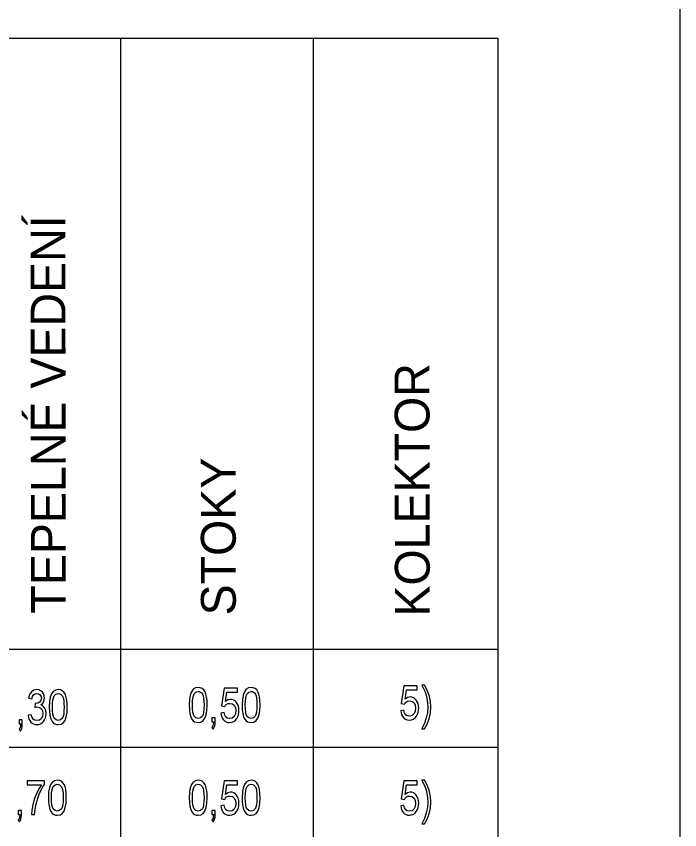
# Model space of a CAD drawing. Extents: x -480568.5 to -480543.1, y -1126945.4 to -1126930.6.
# Drawn here: x -480544.927 to -480543.093, y -1126938.768 to -1126936.519 of the extents above; entities that cross this region are included whole.
import ezdxf

# ---------------------------------------------------------------- set-up
doc = ezdxf.new("R2010")
doc.units = 0
doc.layers.add('detaily', color=7, linetype='Continuous')
doc.layers.add('EL1', color=7, linetype='Continuous')

msp = doc.modelspace()

# ---------------------------------------------------------------- linework, layer by layer
at = {"layer": 'detaily'}
msp.add_line((-480543.0929, -1126930.5663), (-480543.0929, -1126945.4163), dxfattribs=at)
msp.add_lwpolyline([(-480543.5956, -1126939.8124), (-480551.8459, -1126939.8124), (-480551.8459, -1126936.5789), (-480543.5956, -1126936.5789)], close=True, dxfattribs=at)
at = {"layer": 'EL1'}
for p, q in [((-480544.6383, -1126939.8121), (-480544.6383, -1126936.5789)), ((-480544.1063, -1126936.5789), (-480544.1063, -1126939.8121)), ((-480550.8407, -1126938.2688), (-480543.5956, -1126938.2688)), ((-480549.8036, -1126938.5394), (-480543.5956, -1126938.5394))]:
    msp.add_line(p, q, dxfattribs=at)
for points in [[(-480544.8942, -1126938.4517), (-480544.8934, -1126938.4571), (-480544.8919, -1126938.462), (-480544.8897, -1126938.4664), (-480544.8867, -1126938.4702), (-480544.8832, -1126938.4733), (-480544.8793, -1126938.4755), (-480544.8749, -1126938.4769), (-480544.8701, -1126938.4773), (-480544.8648, -1126938.4767), (-480544.86, -1126938.4751), (-480544.8557, -1126938.4723), (-480544.8518, -1126938.4684), (-480544.8486, -1126938.4638), (-480544.8464, -1126938.4586), (-480544.845, -1126938.453), (-480544.8445, -1126938.4468), (-480544.8456, -1126938.4382), (-480544.8486, -1126938.4311), (-480544.8533, -1126938.4259), (-480544.8593, -1126938.4229), (-480544.8548, -1126938.4195), (-480544.8515, -1126938.4151), (-480544.8496, -1126938.41), (-480544.8489, -1126938.4043), (-480544.8496, -1126938.3982), (-480544.8516, -1126938.3925), (-480544.8549, -1126938.3875), (-480544.8594, -1126938.3837), (-480544.8647, -1126938.3813), (-480544.8705, -1126938.3805), (-480544.8786, -1126938.382), (-480544.8852, -1126938.3867), (-480544.8901, -1126938.3942), (-480544.8928, -1126938.4042), (-480544.884, -1126938.406), (-480544.8823, -1126938.3997), (-480544.8793, -1126938.3951), (-480544.8752, -1126938.3923), (-480544.8702, -1126938.3914), (-480544.8652, -1126938.3924), (-480544.8612, -1126938.3952), (-480544.8586, -1126938.3995), (-480544.8577, -1126938.4047), (-480544.8589, -1126938.411), (-480544.8625, -1126938.4155), (-480544.8676, -1126938.4181), (-480544.8733, -1126938.419), (-480544.8748, -1126938.4188), (-480544.8759, -1126938.4298), (-480544.869, -1126938.4285), (-480544.8628, -1126938.4298), (-480544.8577, -1126938.4337), (-480544.8544, -1126938.4395), (-480544.8533, -1126938.4468), (-480544.8544, -1126938.4544), (-480544.8577, -1126938.4607), (-480544.8629, -1126938.4649), (-480544.8698, -1126938.4663), (-480544.8757, -1126938.4654), (-480544.8801, -1126938.4625), (-480544.8833, -1126938.4574), (-480544.8855, -1126938.4499)], [(-480544.8357, -1126938.4289), (-480544.8352, -1126938.4414), (-480544.8338, -1126938.4521), (-480544.8315, -1126938.4612), (-480544.8282, -1126938.4684), (-480544.8248, -1126938.4723), (-480544.8207, -1126938.4751), (-480544.8161, -1126938.4767), (-480544.8109, -1126938.4773), (-480544.8032, -1126938.476), (-480544.797, -1126938.4722), (-480544.7922, -1126938.4657), (-480544.7888, -1126938.4563), (-480544.7867, -1126938.4441), (-480544.786, -1126938.4289), (-480544.7864, -1126938.4163), (-480544.7877, -1126938.4065), (-480544.7897, -1126938.3989), (-480544.7921, -1126938.3924), (-480544.7953, -1126938.3873), (-480544.7997, -1126938.3836), (-480544.805, -1126938.3812), (-480544.8109, -1126938.3805), (-480544.8185, -1126938.3818), (-480544.8247, -1126938.3856), (-480544.8295, -1126938.3921), (-480544.8329, -1126938.4014), (-480544.835, -1126938.4136)], [(-480544.4489, -1126938.4232), (-480544.4484, -1126938.4357), (-480544.447, -1126938.4464), (-480544.4446, -1126938.4554), (-480544.4413, -1126938.4626), (-480544.4379, -1126938.4665), (-480544.4339, -1126938.4693), (-480544.4292, -1126938.471), (-480544.424, -1126938.4715), (-480544.4164, -1126938.4702), (-480544.4102, -1126938.4664), (-480544.4054, -1126938.4599), (-480544.4019, -1126938.4506), (-480544.3999, -1126938.4384), (-480544.3992, -1126938.4232), (-480544.3996, -1126938.4105), (-480544.4009, -1126938.4008), (-480544.4028, -1126938.3931), (-480544.4052, -1126938.3867), (-480544.4085, -1126938.3816), (-480544.4129, -1126938.3778), (-480544.4182, -1126938.3755), (-480544.424, -1126938.3747), (-480544.4316, -1126938.376), (-480544.4378, -1126938.3798), (-480544.4426, -1126938.3864), (-480544.4461, -1126938.3956), (-480544.4482, -1126938.4079)], [(-480544.4401, -1126938.4231), (-480544.4398, -1126938.4128), (-480544.4389, -1126938.4042), (-480544.4374, -1126938.3974), (-480544.4354, -1126938.3922), (-480544.4303, -1126938.3873), (-480544.4241, -1126938.3857), (-480544.4207, -1126938.3862), (-480544.4176, -1126938.3875), (-480544.4148, -1126938.3899), (-480544.4124, -1126938.3931), (-480544.4105, -1126938.3978), (-480544.4091, -1126938.4043), (-480544.4082, -1126938.4128), (-480544.4079, -1126938.4231), (-480544.4082, -1126938.4338), (-480544.4091, -1126938.4425), (-480544.4106, -1126938.4491), (-480544.4126, -1126938.4536), (-480544.4178, -1126938.4588), (-480544.424, -1126938.4606), (-480544.4303, -1126938.4588), (-480544.4355, -1126938.4536), (-480544.4375, -1126938.4491), (-480544.439, -1126938.4425), (-480544.4398, -1126938.4339)], [(-480544.3611, -1126938.446), (-480544.3603, -1126938.4515), (-480544.3588, -1126938.4564), (-480544.3566, -1126938.4608), (-480544.3537, -1126938.4645), (-480544.3503, -1126938.4676), (-480544.3463, -1126938.4698), (-480544.3419, -1126938.4711), (-480544.337, -1126938.4715), (-480544.3311, -1126938.4708), (-480544.3259, -1126938.4687), (-480544.3213, -1126938.4651), (-480544.3173, -1126938.4601), (-480544.3148, -1126938.4553), (-480544.3129, -1126938.45), (-480544.3118, -1126938.4443), (-480544.3114, -1126938.4381), (-480544.3118, -1126938.4317), (-480544.3131, -1126938.4259), (-480544.3152, -1126938.4207), (-480544.3182, -1126938.4161), (-480544.3218, -1126938.4124), (-480544.3257, -1126938.4097), (-480544.33, -1126938.4081), (-480544.3347, -1126938.4076), (-480544.342, -1126938.4092), (-480544.3489, -1126938.4139), (-480544.3451, -1126938.3875), (-480544.3158, -1126938.3875), (-480544.3158, -1126938.3765), (-480544.3523, -1126938.3765), (-480544.3596, -1126938.4259), (-480544.3509, -1126938.4277), (-480544.3485, -1126938.424), (-480544.3454, -1126938.4211), (-480544.3416, -1126938.4192), (-480544.3367, -1126938.4186), (-480544.3294, -1126938.4199), (-480544.3242, -1126938.424), (-480544.3212, -1126938.4304), (-480544.3202, -1126938.4388), (-480544.3213, -1126938.4477), (-480544.3245, -1126938.4546), (-480544.3298, -1126938.4591), (-480544.337, -1126938.4606), (-480544.3429, -1126938.4596), (-480544.3474, -1126938.4565), (-480544.3505, -1126938.4513), (-480544.3523, -1126938.4441)], [(-480544.3026, -1126938.4232), (-480544.3021, -1126938.4357), (-480544.3007, -1126938.4464), (-480544.2984, -1126938.4554), (-480544.295, -1126938.4626), (-480544.2916, -1126938.4665), (-480544.2876, -1126938.4693), (-480544.283, -1126938.471), (-480544.2777, -1126938.4715), (-480544.2701, -1126938.4702), (-480544.2639, -1126938.4664), (-480544.2591, -1126938.4599), (-480544.2557, -1126938.4506), (-480544.2536, -1126938.4384), (-480544.2529, -1126938.4232), (-480544.2533, -1126938.4105), (-480544.2546, -1126938.4008), (-480544.2566, -1126938.3931), (-480544.259, -1126938.3867), (-480544.2622, -1126938.3816), (-480544.2666, -1126938.3778), (-480544.2719, -1126938.3755), (-480544.2777, -1126938.3747), (-480544.2853, -1126938.376), (-480544.2915, -1126938.3798), (-480544.2963, -1126938.3864), (-480544.2998, -1126938.3956), (-480544.3019, -1126938.4079)], [(-480544.2938, -1126938.4231), (-480544.2935, -1126938.4128), (-480544.2926, -1126938.4042), (-480544.2912, -1126938.3974), (-480544.2891, -1126938.3922), (-480544.2841, -1126938.3873), (-480544.2778, -1126938.3857), (-480544.2744, -1126938.3862), (-480544.2713, -1126938.3875), (-480544.2685, -1126938.3899), (-480544.2661, -1126938.3931), (-480544.2642, -1126938.3978), (-480544.2628, -1126938.4043), (-480544.2619, -1126938.4128), (-480544.2617, -1126938.4231), (-480544.2619, -1126938.4338), (-480544.2628, -1126938.4425), (-480544.2643, -1126938.4491), (-480544.2663, -1126938.4536), (-480544.2715, -1126938.4588), (-480544.2777, -1126938.4606), (-480544.284, -1126938.4588), (-480544.2892, -1126938.4536), (-480544.2912, -1126938.4491), (-480544.2927, -1126938.4425), (-480544.2935, -1126938.4339)], [(-480543.8641, -1126938.4394), (-480543.8633, -1126938.4449), (-480543.8619, -1126938.4498), (-480543.8597, -1126938.4542), (-480543.8568, -1126938.458), (-480543.8533, -1126938.4611), (-480543.8494, -1126938.4632), (-480543.845, -1126938.4645), (-480543.8401, -1126938.465), (-480543.8342, -1126938.4643), (-480543.8289, -1126938.4621), (-480543.8243, -1126938.4586), (-480543.8204, -1126938.4536), (-480543.8178, -1126938.4487), (-480543.8159, -1126938.4434), (-480543.8148, -1126938.4377), (-480543.8144, -1126938.4315), (-480543.8149, -1126938.4251), (-480543.8161, -1126938.4193), (-480543.8183, -1126938.4142), (-480543.8212, -1126938.4096), (-480543.8248, -1126938.4058), (-480543.8287, -1126938.4032), (-480543.8331, -1126938.4016), (-480543.8378, -1126938.401), (-480543.845, -1126938.4026), (-480543.8519, -1126938.4074), (-480543.8481, -1126938.3809), (-480543.8188, -1126938.3809), (-480543.8188, -1126938.37), (-480543.8554, -1126938.37), (-480543.8627, -1126938.4193), (-480543.8539, -1126938.4211), (-480543.8515, -1126938.4175), (-480543.8485, -1126938.4145), (-480543.8446, -1126938.4126), (-480543.8398, -1126938.412), (-480543.8324, -1126938.4134), (-480543.8273, -1126938.4174), (-480543.8242, -1126938.4238), (-480543.8232, -1126938.4322), (-480543.8243, -1126938.4411), (-480543.8276, -1126938.448), (-480543.8329, -1126938.4525), (-480543.84, -1126938.454), (-480543.846, -1126938.453), (-480543.8504, -1126938.4499), (-480543.8536, -1126938.4448), (-480543.8554, -1126938.4376)], [(-480543.7983, -1126938.4887), (-480543.7915, -1126938.4759), (-480543.7859, -1126938.4611), (-480543.782, -1126938.445), (-480543.7808, -1126938.4284), (-480543.7817, -1126938.4138), (-480543.7846, -1126938.3998), (-480543.7902, -1126938.3839), (-480543.7983, -1126938.3681), (-480543.8056, -1126938.3681), (-480543.797, -1126938.387), (-480543.794, -1126938.3958), (-480543.7918, -1126938.405), (-480543.7901, -1126938.4167), (-480543.7895, -1126938.4284), (-480543.7905, -1126938.4435), (-480543.7936, -1126938.4586), (-480543.7986, -1126938.4737), (-480543.8056, -1126938.4887)], [(-480544.8269, -1126938.4289), (-480544.8267, -1126938.4185), (-480544.8258, -1126938.4099), (-480544.8243, -1126938.4031), (-480544.8222, -1126938.398), (-480544.8172, -1126938.3931), (-480544.811, -1126938.3914), (-480544.8075, -1126938.3919), (-480544.8044, -1126938.3933), (-480544.8017, -1126938.3956), (-480544.7992, -1126938.3989), (-480544.7973, -1126938.4035), (-480544.7959, -1126938.4101), (-480544.7951, -1126938.4186), (-480544.7948, -1126938.4289), (-480544.7951, -1126938.4396), (-480544.7959, -1126938.4482), (-480544.7974, -1126938.4548), (-480544.7994, -1126938.4593), (-480544.8046, -1126938.4646), (-480544.8109, -1126938.4663), (-480544.8171, -1126938.4646), (-480544.8223, -1126938.4593), (-480544.8244, -1126938.4548), (-480544.8258, -1126938.4482), (-480544.8267, -1126938.4396)], [(-480544.9191, -1126938.4755), (-480544.9147, -1126938.4755), (-480544.9159, -1126938.4851), (-480544.9172, -1126938.488), (-480544.9191, -1126938.4901), (-480544.9162, -1126938.4956), (-480544.9136, -1126938.4924), (-480544.9117, -1126938.4881), (-480544.9107, -1126938.4825), (-480544.9103, -1126938.4755), (-480544.9103, -1126938.4645), (-480544.9191, -1126938.4645)], [(-480544.386, -1126938.4697), (-480544.3816, -1126938.4697), (-480544.3827, -1126938.4793), (-480544.3841, -1126938.4822), (-480544.386, -1126938.4843), (-480544.383, -1126938.4898), (-480544.3804, -1126938.4866), (-480544.3786, -1126938.4824), (-480544.3775, -1126938.4768), (-480544.3772, -1126938.4697), (-480544.3772, -1126938.4588), (-480544.386, -1126938.4588)], [(-480544.8969, -1126938.6439), (-480544.8574, -1126938.6439), (-480544.8646, -1126938.6552), (-480544.8714, -1126938.6687), (-480544.8772, -1126938.6836), (-480544.8815, -1126938.6991), (-480544.8842, -1126938.7138), (-480544.8852, -1126938.7261), (-480544.8764, -1126938.7261), (-480544.8752, -1126938.7125), (-480544.873, -1126938.7001), (-480544.8685, -1126938.6835), (-480544.8624, -1126938.6673), (-480544.8556, -1126938.653), (-480544.8486, -1126938.6418), (-480544.8486, -1126938.6329), (-480544.8969, -1126938.6329)], [(-480544.8383, -1126938.6795), (-480544.8379, -1126938.6921), (-480544.8365, -1126938.7028), (-480544.8341, -1126938.7118), (-480544.8308, -1126938.719), (-480544.8274, -1126938.7229), (-480544.8234, -1126938.7257), (-480544.8187, -1126938.7274), (-480544.8135, -1126938.7279), (-480544.8059, -1126938.7266), (-480544.7997, -1126938.7228), (-480544.7949, -1126938.7163), (-480544.7914, -1126938.707), (-480544.7894, -1126938.6948), (-480544.7887, -1126938.6795), (-480544.7891, -1126938.6669), (-480544.7904, -1126938.6571), (-480544.7923, -1126938.6495), (-480544.7947, -1126938.643), (-480544.798, -1126938.638), (-480544.8024, -1126938.6342), (-480544.8077, -1126938.6319), (-480544.8135, -1126938.6311), (-480544.8211, -1126938.6324), (-480544.8273, -1126938.6362), (-480544.8321, -1126938.6428), (-480544.8356, -1126938.652), (-480544.8377, -1126938.6643)], [(-480544.4489, -1126938.6795), (-480544.4484, -1126938.6921), (-480544.447, -1126938.7028), (-480544.4446, -1126938.7118), (-480544.4413, -1126938.719), (-480544.4379, -1126938.7229), (-480544.4339, -1126938.7257), (-480544.4292, -1126938.7274), (-480544.424, -1126938.7279), (-480544.4164, -1126938.7266), (-480544.4102, -1126938.7228), (-480544.4054, -1126938.7163), (-480544.4019, -1126938.707), (-480544.3999, -1126938.6948), (-480544.3992, -1126938.6795), (-480544.3996, -1126938.6669), (-480544.4009, -1126938.6571), (-480544.4028, -1126938.6495), (-480544.4052, -1126938.643), (-480544.4085, -1126938.638), (-480544.4129, -1126938.6342), (-480544.4182, -1126938.6319), (-480544.424, -1126938.6311), (-480544.4316, -1126938.6324), (-480544.4378, -1126938.6362), (-480544.4426, -1126938.6428), (-480544.4461, -1126938.652), (-480544.4482, -1126938.6643)], [(-480544.3611, -1126938.7024), (-480544.3603, -1126938.7079), (-480544.3588, -1126938.7128), (-480544.3566, -1126938.7172), (-480544.3537, -1126938.7209), (-480544.3503, -1126938.724), (-480544.3463, -1126938.7262), (-480544.3419, -1126938.7275), (-480544.337, -1126938.7279), (-480544.3311, -1126938.7272), (-480544.3259, -1126938.7251), (-480544.3213, -1126938.7215), (-480544.3173, -1126938.7165), (-480544.3148, -1126938.7117), (-480544.3129, -1126938.7064), (-480544.3118, -1126938.7006), (-480544.3114, -1126938.6945), (-480544.3118, -1126938.6881), (-480544.3131, -1126938.6823), (-480544.3152, -1126938.6771), (-480544.3182, -1126938.6725), (-480544.3218, -1126938.6688), (-480544.3257, -1126938.6661), (-480544.33, -1126938.6645), (-480544.3347, -1126938.664), (-480544.342, -1126938.6656), (-480544.3489, -1126938.6703), (-480544.3451, -1126938.6439), (-480544.3158, -1126938.6439), (-480544.3158, -1126938.6329), (-480544.3523, -1126938.6329), (-480544.3596, -1126938.6823), (-480544.3509, -1126938.6841), (-480544.3485, -1126938.6804), (-480544.3454, -1126938.6775), (-480544.3416, -1126938.6756), (-480544.3367, -1126938.675), (-480544.3294, -1126938.6763), (-480544.3242, -1126938.6804), (-480544.3212, -1126938.6868), (-480544.3202, -1126938.6952), (-480544.3213, -1126938.7041), (-480544.3245, -1126938.711), (-480544.3298, -1126938.7155), (-480544.337, -1126938.717), (-480544.3429, -1126938.716), (-480544.3474, -1126938.7129), (-480544.3505, -1126938.7077), (-480544.3523, -1126938.7005)], [(-480544.3026, -1126938.6795), (-480544.3021, -1126938.6921), (-480544.3007, -1126938.7028), (-480544.2984, -1126938.7118), (-480544.295, -1126938.719), (-480544.2916, -1126938.7229), (-480544.2876, -1126938.7257), (-480544.283, -1126938.7274), (-480544.2777, -1126938.7279), (-480544.2701, -1126938.7266), (-480544.2639, -1126938.7228), (-480544.2591, -1126938.7163), (-480544.2557, -1126938.707), (-480544.2536, -1126938.6948), (-480544.2529, -1126938.6795), (-480544.2533, -1126938.6669), (-480544.2546, -1126938.6571), (-480544.2566, -1126938.6495), (-480544.259, -1126938.643), (-480544.2622, -1126938.638), (-480544.2666, -1126938.6342), (-480544.2719, -1126938.6319), (-480544.2777, -1126938.6311), (-480544.2853, -1126938.6324), (-480544.2915, -1126938.6362), (-480544.2963, -1126938.6428), (-480544.2998, -1126938.652), (-480544.3019, -1126938.6643)], [(-480543.8641, -1126938.7024), (-480543.8633, -1126938.7079), (-480543.8619, -1126938.7128), (-480543.8597, -1126938.7172), (-480543.8568, -1126938.7209), (-480543.8533, -1126938.724), (-480543.8494, -1126938.7262), (-480543.845, -1126938.7275), (-480543.8401, -1126938.7279), (-480543.8342, -1126938.7272), (-480543.8289, -1126938.7251), (-480543.8243, -1126938.7215), (-480543.8204, -1126938.7165), (-480543.8178, -1126938.7117), (-480543.8159, -1126938.7064), (-480543.8148, -1126938.7006), (-480543.8144, -1126938.6945), (-480543.8149, -1126938.6881), (-480543.8161, -1126938.6823), (-480543.8183, -1126938.6771), (-480543.8212, -1126938.6725), (-480543.8248, -1126938.6688), (-480543.8287, -1126938.6661), (-480543.8331, -1126938.6645), (-480543.8378, -1126938.664), (-480543.845, -1126938.6656), (-480543.8519, -1126938.6703), (-480543.8481, -1126938.6439), (-480543.8188, -1126938.6439), (-480543.8188, -1126938.6329), (-480543.8554, -1126938.6329), (-480543.8627, -1126938.6823), (-480543.8539, -1126938.6841), (-480543.8515, -1126938.6804), (-480543.8485, -1126938.6775), (-480543.8446, -1126938.6756), (-480543.8398, -1126938.675), (-480543.8324, -1126938.6763), (-480543.8273, -1126938.6804), (-480543.8242, -1126938.6868), (-480543.8232, -1126938.6952), (-480543.8243, -1126938.7041), (-480543.8276, -1126938.711), (-480543.8329, -1126938.7155), (-480543.84, -1126938.717), (-480543.846, -1126938.716), (-480543.8504, -1126938.7129), (-480543.8536, -1126938.7077), (-480543.8554, -1126938.7005)], [(-480543.7983, -1126938.7517), (-480543.7915, -1126938.7389), (-480543.7859, -1126938.7241), (-480543.782, -1126938.708), (-480543.7808, -1126938.6913), (-480543.7817, -1126938.6768), (-480543.7846, -1126938.6627), (-480543.7902, -1126938.6469), (-480543.7983, -1126938.6311), (-480543.8056, -1126938.6311), (-480543.797, -1126938.6499), (-480543.794, -1126938.6588), (-480543.7918, -1126938.668), (-480543.7901, -1126938.6797), (-480543.7895, -1126938.6914), (-480543.7905, -1126938.7065), (-480543.7936, -1126938.7216), (-480543.7986, -1126938.7366), (-480543.8056, -1126938.7517)], [(-480544.8296, -1126938.6795), (-480544.8293, -1126938.6692), (-480544.8284, -1126938.6606), (-480544.8269, -1126938.6537), (-480544.8248, -1126938.6486), (-480544.8198, -1126938.6437), (-480544.8136, -1126938.6421), (-480544.8102, -1126938.6426), (-480544.8071, -1126938.6439), (-480544.8043, -1126938.6463), (-480544.8019, -1126938.6495), (-480544.8, -1126938.6542), (-480544.7985, -1126938.6607), (-480544.7977, -1126938.6692), (-480544.7974, -1126938.6795), (-480544.7977, -1126938.6902), (-480544.7986, -1126938.6989), (-480544.8001, -1126938.7054), (-480544.8021, -1126938.71), (-480544.8072, -1126938.7152), (-480544.8135, -1126938.717), (-480544.8198, -1126938.7152), (-480544.8249, -1126938.71), (-480544.827, -1126938.7055), (-480544.8284, -1126938.6989), (-480544.8293, -1126938.6903)], [(-480544.4401, -1126938.6795), (-480544.4398, -1126938.6692), (-480544.4389, -1126938.6606), (-480544.4374, -1126938.6537), (-480544.4354, -1126938.6486), (-480544.4303, -1126938.6437), (-480544.4241, -1126938.6421), (-480544.4207, -1126938.6426), (-480544.4176, -1126938.6439), (-480544.4148, -1126938.6463), (-480544.4124, -1126938.6495), (-480544.4105, -1126938.6542), (-480544.4091, -1126938.6607), (-480544.4082, -1126938.6692), (-480544.4079, -1126938.6795), (-480544.4082, -1126938.6902), (-480544.4091, -1126938.6989), (-480544.4106, -1126938.7054), (-480544.4126, -1126938.71), (-480544.4178, -1126938.7152), (-480544.424, -1126938.717), (-480544.4303, -1126938.7152), (-480544.4355, -1126938.71), (-480544.4375, -1126938.7055), (-480544.439, -1126938.6989), (-480544.4398, -1126938.6903)], [(-480544.2938, -1126938.6795), (-480544.2935, -1126938.6692), (-480544.2926, -1126938.6606), (-480544.2912, -1126938.6537), (-480544.2891, -1126938.6486), (-480544.2841, -1126938.6437), (-480544.2778, -1126938.6421), (-480544.2744, -1126938.6426), (-480544.2713, -1126938.6439), (-480544.2685, -1126938.6463), (-480544.2661, -1126938.6495), (-480544.2642, -1126938.6542), (-480544.2628, -1126938.6607), (-480544.2619, -1126938.6692), (-480544.2617, -1126938.6795), (-480544.2619, -1126938.6902), (-480544.2628, -1126938.6989), (-480544.2643, -1126938.7054), (-480544.2663, -1126938.71), (-480544.2715, -1126938.7152), (-480544.2777, -1126938.717), (-480544.284, -1126938.7152), (-480544.2892, -1126938.71), (-480544.2912, -1126938.7055), (-480544.2927, -1126938.6989), (-480544.2935, -1126938.6903)], [(-480544.9217, -1126938.7261), (-480544.9174, -1126938.7261), (-480544.9185, -1126938.7357), (-480544.9198, -1126938.7386), (-480544.9217, -1126938.7407), (-480544.9188, -1126938.7462), (-480544.9162, -1126938.743), (-480544.9144, -1126938.7387), (-480544.9133, -1126938.7332), (-480544.913, -1126938.7261), (-480544.913, -1126938.7152), (-480544.9217, -1126938.7152)], [(-480544.386, -1126938.7261), (-480544.3816, -1126938.7261), (-480544.3827, -1126938.7357), (-480544.3841, -1126938.7386), (-480544.386, -1126938.7407), (-480544.383, -1126938.7462), (-480544.3804, -1126938.743), (-480544.3786, -1126938.7387), (-480544.3775, -1126938.7332), (-480544.3772, -1126938.7261), (-480544.3772, -1126938.7152), (-480544.386, -1126938.7152)]]:
    msp.add_lwpolyline(points, close=True, dxfattribs=at)

# ---------------------------------------------------------------- texts
for s, height, p in [('TEPELNÉ VEDENÍ', 0.096228, (-480544.79, -1126938.1704)), ('KOLEKTOR', 0.09623, (-480543.7839, -1126938.1786)), ('STOKY', 0.09623, (-480544.3201, -1126938.1754))]:
    msp.add_text(s, height=height, rotation=90.0721, dxfattribs=at).set_placement(p)

doc.saveas('drawing.dxf')
